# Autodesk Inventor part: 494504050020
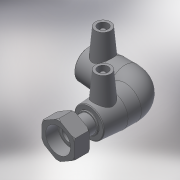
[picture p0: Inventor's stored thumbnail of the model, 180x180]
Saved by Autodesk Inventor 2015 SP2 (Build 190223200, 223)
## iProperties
Created: 2017-06
Part Number: 494504050020
Material: Generic
Description: PLASSON 90° ELBOW FEMALE FREE NUT TRANSITION 50-2"
Document SubType Name: Modeling
Designer: KIM
Mass: 55.0731 g
Surface Area: 148.067 cm^2
Volume: 55.0731 cm^3
Density: 1 g/cm^3
Appearance: Default
Author: KIM
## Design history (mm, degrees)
derived "494504.ipt"
feature "Solid1::494504.ipt"
tag "TaggingFeature1"
body "Solid1"
other parameters: "d2" = 67, "d4" = 36, "d5" = 60.3, "d8" = 168 deg, "d10" = 19.2, "d11" = 6.4, "d29" = 52, "d30" = 15, "d31" = 59.4, "d34" = 5 deg, "d41" = 4, "d42" = 14, "d43" = 0, "d48" = 74.5, "d50" = 42.5, "d51" = 19.2, "d52" = 48, "d54" = 90 deg, "d58" = 48, "d59" = 0, "d61" = 90 deg, "d86" = 3, "d87" = 0, "d97" = 38, "d98" = 41, "d99" = 84.984, "d109" = 1.5, "d116" = 20.5, "d117" = 56.656, "d118" = 16.4, "d119" = 1.64, "d120" = 45.3248, "d121" = 1.64, "d122" = 39.6592, "d123" = 38, "d124" = 2.8328, "d128" = 0, "L_" = 149, "L_1" = 48, "D_" = 38, "A_" = 52, "d_2" = 12, "L_2" = 41, "D_1" = 67, "G_" = 56.656
